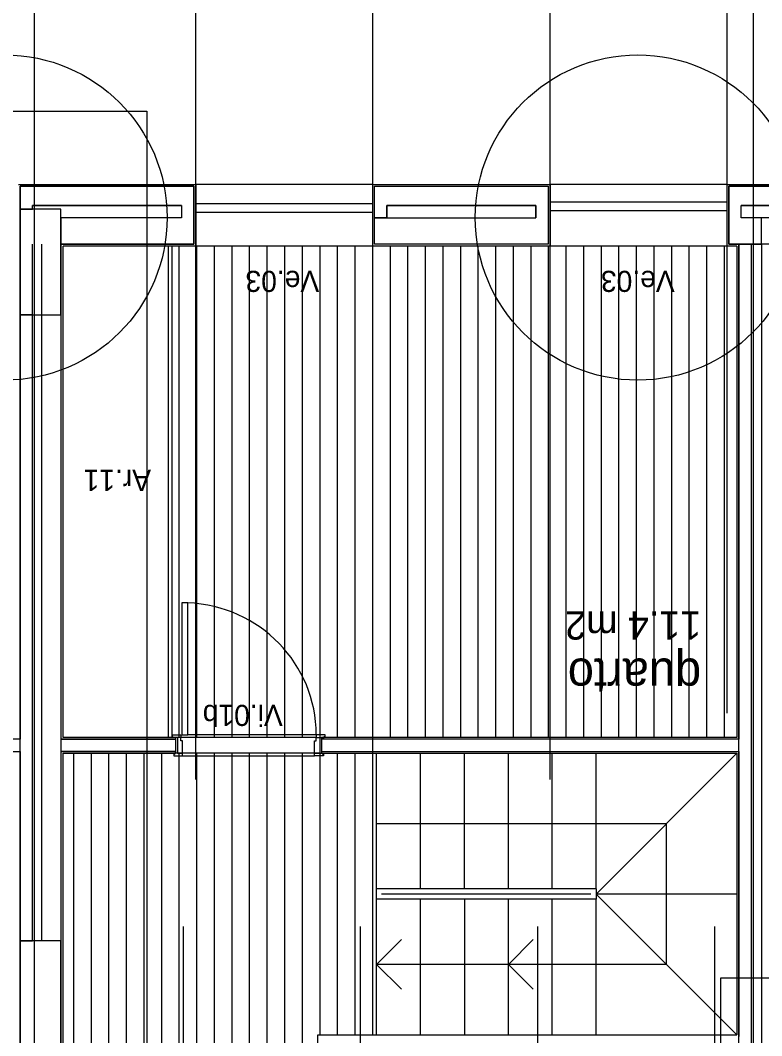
# Model space of a CAD drawing. Extents: x 1278 to 1356, y -253.7 to -224.
# Drawn here: x 1311.39 to 1315.61, y -236.76 to -230.99 of the extents above; entities that cross this region are included whole.
import ezdxf

# ---------------------------------------------------------------- set-up
doc = ezdxf.new("R2010")
doc.units = 0
for name, color, linetype in [('Level 1', 7, 'Continuous'), ('Level 10', 7, 'Continuous'), ('Level 13', 7, 'Continuous'), ('Level 2', 7, 'Continuous'), ('Level 4', 7, 'Continuous'), ('Level 40', 7, 'Continuous'), ('Level 59', 7, 'Continuous'), ('Level 60', 7, 'Continuous'), ('Level 65', 7, 'Continuous'), ('Level 66', 7, 'Continuous'), ('Level 67', 7, 'Continuous'), ('Level 69', 7, 'Continuous'), ('Level 70', 7, 'Continuous'), ('Level 93', 7, 'Continuous')]:
    doc.layers.add(name, color=color, linetype=linetype)

msp = doc.modelspace()

# ---------------------------------------------------------------- linework, layer by layer
at = {"layer": 'Level 1'}
for p, q in [((1311.389, -231.934), (1312.3765, -231.934)), ((1312.3765, -231.934), (1312.3765, -232.264)), ((1313.404, -231.934), (1314.3915, -231.934)), ((1313.404, -232.264), (1313.404, -231.934)), ((1314.3915, -231.934), (1314.3915, -232.264)), ((1315.419, -231.934), (1317.2844, -231.934)), ((1315.419, -232.264), (1315.419, -231.934)), ((1311.459, -232.0639), (1311.459, -232.044)), ((1312.3065, -232.044), (1312.3065, -232.1143)), ((1313.474, -232.1143), (1313.474, -232.044)), ((1314.3215, -232.044), (1314.3215, -232.1143)), ((1315.489, -232.1143), (1315.489, -232.044)), ((1312.3765, -232.264), (1311.6219, -232.264)), ((1314.3915, -232.264), (1313.404, -232.264)), ((1315.6044, -232.264), (1315.419, -232.264)), ((1312.2723, -235.0752), (1311.6219, -235.0752)), ((1312.2723, -235.0652), (1312.2723, -235.1552)), ((1313.1023, -235.0652), (1313.1023, -235.0752)), ((1313.1023, -235.0652), (1313.1023, -235.1552)), ((1311.6219, -235.1452), (1312.2723, -235.1452)), ((1313.1023, -235.1452), (1313.1023, -235.1552)), ((1313.1023, -235.1452), (1315.4744, -235.1452))]:
    msp.add_line(p, q, dxfattribs=at)
for points in [[(1317.2844, -232.264), (1315.6044, -232.264)], [(1315.4744, -235.0752), (1313.1023, -235.0752)]]:
    msp.add_lwpolyline(points, dxfattribs=at)
at = {"layer": 'Level 10'}
for p, q in [((1312.2933, -235.0652), (1312.2933, -232.274)), ((1312.3933, -235.0652), (1312.3933, -232.274)), ((1312.4933, -235.0652), (1312.4933, -232.274)), ((1312.5933, -235.0652), (1312.5933, -232.274)), ((1312.6933, -235.0652), (1312.6933, -232.274)), ((1312.7933, -235.0652), (1312.7933, -232.274)), ((1312.8933, -235.0652), (1312.8933, -232.274)), ((1312.9933, -235.0652), (1312.9933, -232.274)), ((1313.0933, -235.0652), (1313.0933, -232.274)), ((1313.1933, -235.0652), (1313.1933, -232.274)), ((1313.2933, -235.0652), (1313.2933, -232.274)), ((1313.3933, -235.0652), (1313.3933, -232.274)), ((1313.4933, -235.0652), (1313.4933, -232.274)), ((1313.5933, -235.0652), (1313.5933, -232.274)), ((1313.6933, -235.0652), (1313.6933, -232.274)), ((1313.7933, -235.0652), (1313.7933, -232.274)), ((1313.8933, -235.0652), (1313.8933, -232.274)), ((1313.9933, -235.0652), (1313.9933, -232.274)), ((1314.0933, -235.0652), (1314.0933, -232.274)), ((1314.1933, -235.0652), (1314.1933, -232.274)), ((1314.2933, -235.0652), (1314.2933, -232.274)), ((1314.3933, -235.0652), (1314.3933, -232.274)), ((1314.4933, -235.0652), (1314.4933, -232.274)), ((1314.5933, -235.0652), (1314.5933, -232.274)), ((1314.6933, -235.0652), (1314.6933, -232.274)), ((1314.7933, -235.0652), (1314.7933, -232.274)), ((1314.8933, -235.0652), (1314.8933, -232.274)), ((1314.9933, -235.0652), (1314.9933, -232.274)), ((1315.0933, -235.0652), (1315.0933, -232.274)), ((1315.1933, -235.0652), (1315.1933, -232.274)), ((1315.2933, -235.0652), (1315.2933, -232.274)), ((1315.3933, -235.0652), (1315.3933, -232.274)), ((1313.0723, -235.0652), (1312.3023, -235.0652)), ((1311.6933, -243.574), (1311.6933, -235.1552)), ((1311.7933, -243.574), (1311.7933, -235.1552)), ((1311.8933, -243.574), (1311.8933, -235.1552)), ((1311.9933, -243.574), (1311.9933, -235.1552)), ((1312.0933, -243.574), (1312.0933, -235.1552)), ((1312.1933, -243.574), (1312.1933, -235.1552)), ((1312.2933, -243.574), (1312.2933, -235.1552)), ((1313.0623, -235.1552), (1312.3123, -235.1552)), ((1312.3933, -243.574), (1312.3933, -235.1552)), ((1312.4933, -243.574), (1312.4933, -235.1552)), ((1312.5933, -243.574), (1312.5933, -235.1552)), ((1312.6933, -243.574), (1312.6933, -235.1552)), ((1312.7933, -243.574), (1312.7933, -235.1552)), ((1312.8933, -243.574), (1312.8933, -235.1552)), ((1312.9933, -243.574), (1312.9933, -235.1552)), ((1313.0933, -236.7552), (1313.0933, -235.1552)), ((1313.1933, -236.7552), (1313.1933, -235.1552)), ((1313.2933, -236.7552), (1313.2933, -235.1552)), ((1313.3933, -236.7552), (1313.3933, -235.1552))]:
    msp.add_line(p, q, dxfattribs=at)
at = {"layer": 'Level 13'}
for p, q in [((1312.2323, -235.0652), (1312.2323, -232.274)), ((1312.2523, -235.0652), (1312.2523, -232.274)), ((1312.3073, -234.3002), (1312.3073, -235.0502)), ((1312.3423, -234.3002), (1312.3073, -234.3002)), ((1312.3423, -235.0502), (1312.3423, -234.3002)), ((1312.2523, -235.0502), (1312.3023, -235.0502)), ((1312.2523, -235.0602), (1312.2523, -235.0502)), ((1312.2573, -235.0602), (1312.2523, -235.0602)), ((1312.2573, -235.0652), (1312.2573, -235.0602)), ((1312.3023, -235.0652), (1312.2573, -235.0652)), ((1312.2823, -235.0652), (1312.2823, -235.1552)), ((1312.3023, -235.0652), (1312.2823, -235.0652)), ((1312.3023, -235.0502), (1312.3023, -235.0652)), ((1312.3023, -235.0852), (1312.3023, -235.0652)), ((1312.3073, -235.0502), (1312.3423, -235.0502)), ((1313.1223, -235.0502), (1313.0723, -235.0502)), ((1313.0723, -235.0502), (1313.0723, -235.0652)), ((1313.0723, -235.0852), (1313.0723, -235.0652)), ((1313.0723, -235.0652), (1313.0923, -235.0652)), ((1313.0723, -235.0652), (1313.1173, -235.0652)), ((1313.0923, -235.0652), (1313.0923, -235.1552)), ((1313.1173, -235.0652), (1313.1173, -235.0602)), ((1313.1173, -235.0602), (1313.1223, -235.0602)), ((1313.1223, -235.0602), (1313.1223, -235.0502)), ((1312.3123, -235.0852), (1312.3023, -235.0852)), ((1312.3123, -235.1552), (1312.3123, -235.0852)), ((1313.0623, -235.1552), (1313.0623, -235.0852)), ((1313.0623, -235.0852), (1313.0723, -235.0852)), ((1312.2673, -235.1602), (1312.2623, -235.1602)), ((1312.2623, -235.1602), (1312.2623, -235.1702)), ((1312.2623, -235.1702), (1312.3123, -235.1702)), ((1312.3123, -235.1552), (1312.2673, -235.1552)), ((1312.2673, -235.1552), (1312.2673, -235.1602)), ((1312.2823, -235.1552), (1312.3123, -235.1552)), ((1312.3123, -235.1702), (1312.3123, -235.1552)), ((1313.0923, -235.1552), (1313.0623, -235.1552)), ((1313.0623, -235.1702), (1313.0623, -235.1552)), ((1313.0623, -235.1552), (1313.1073, -235.1552)), ((1313.1123, -235.1702), (1313.0623, -235.1702)), ((1313.1073, -235.1552), (1313.1073, -235.1602)), ((1313.1073, -235.1602), (1313.1123, -235.1602)), ((1313.1123, -235.1602), (1313.1123, -235.1702))]:
    msp.add_line(p, q, dxfattribs=at)
at = {"layer": 'Level 2'}
for p, q in [((1313.394, -231.924), (1312.3865, -231.924)), ((1315.409, -231.924), (1314.4015, -231.924)), ((1313.394, -232.034), (1312.3865, -232.034)), ((1315.409, -232.024), (1314.4015, -232.024)), ((1315.409, -232.074), (1314.4015, -232.074)), ((1313.394, -232.084), (1312.3865, -232.084)), ((1313.394, -232.274), (1312.3865, -232.274)), ((1315.409, -232.274), (1314.4015, -232.274)), ((1313.4144, -235.9252), (1313.4144, -235.1552)), ((1313.6644, -235.9252), (1313.6644, -235.1552)), ((1313.9144, -235.9252), (1313.9144, -235.1552)), ((1314.1644, -235.9252), (1314.1644, -235.1552)), ((1314.4144, -235.9252), (1314.4144, -235.1552)), ((1314.6644, -235.9252), (1314.6644, -235.1552)), ((1314.6644, -235.9552), (1315.4644, -235.1552)), ((1313.4144, -235.5552), (1315.0644, -235.5552)), ((1315.0644, -236.3552), (1315.0644, -235.5552)), ((1314.6644, -235.9252), (1313.4144, -235.9252)), ((1313.4144, -235.9852), (1313.4144, -235.9252)), ((1314.6644, -235.9252), (1314.6644, -235.9852)), ((1313.4144, -236.7552), (1313.4144, -235.9852)), ((1314.6644, -235.9852), (1313.4144, -235.9852)), ((1314.6325, -235.9552), (1313.4435, -235.9552)), ((1313.6644, -236.7552), (1313.6644, -235.9852)), ((1313.9144, -235.9852), (1313.9144, -236.7552)), ((1314.1644, -236.7552), (1314.1644, -235.9852)), ((1314.4144, -236.7552), (1314.4144, -235.9852)), ((1315.4644, -235.9552), (1314.6644, -235.9552)), ((1314.6644, -235.9552), (1315.4644, -236.7552)), ((1314.6644, -236.7552), (1314.6644, -235.9852)), ((1313.5558, -236.2137), (1313.4144, -236.3552)), ((1314.3058, -236.2137), (1314.1644, -236.3552)), ((1313.5558, -236.4966), (1313.4144, -236.3552)), ((1314.1644, -236.3552), (1313.4144, -236.3552)), ((1315.0644, -236.3552), (1314.1644, -236.3552)), ((1314.3058, -236.4966), (1314.1644, -236.3552))]:
    msp.add_line(p, q, dxfattribs=at)
at = {"layer": 'Level 4'}
for p, q in [((1313.0723, -235.0502), (1312.3423, -235.0502)), ((1312.3123, -235.1702), (1313.0623, -235.1702))]:
    msp.add_line(p, q, dxfattribs=at)
msp.add_ellipse((1312.3091, -235.0502), major_axis=(-0.7632, 0), ratio=0.982661, start_param=3.141593, end_param=4.668897, dxfattribs=at)
at = {"layer": 'Level 59'}
msp.add_lwpolyline([(1312.108, -245.3846), (1306.9649, -245.3846), (1306.9649, -231.5072), (1312.108, -231.5072)], close=True, dxfattribs=at)
at = {"layer": 'Level 65'}
for p, q in [((1311.379, -231.924), (1312.3865, -231.924)), ((1312.3865, -231.924), (1312.3865, -232.274)), ((1313.394, -232.274), (1313.394, -231.924)), ((1313.394, -231.924), (1314.4015, -231.924)), ((1314.4015, -231.924), (1314.4015, -232.274)), ((1315.409, -231.924), (1317.2944, -231.924)), ((1315.409, -232.274), (1315.409, -231.924)), ((1312.3865, -232.274), (1311.6319, -232.274)), ((1311.6319, -235.0652), (1311.6319, -232.274)), ((1311.6319, -235.0652), (1311.6319, -232.274)), ((1311.6319, -235.0652), (1311.6319, -232.274)), ((1314.4015, -232.274), (1313.394, -232.274)), ((1315.4644, -232.274), (1315.4644, -235.0652)), ((1312.2723, -235.0652), (1311.6319, -235.0652)), ((1311.6319, -235.1552), (1312.2723, -235.1552)), ((1311.6319, -243.574), (1311.6319, -235.1552)), ((1311.6319, -240.7363), (1311.6319, -235.1552)), ((1313.1023, -235.1552), (1315.4644, -235.1552)), ((1315.4644, -235.1552), (1315.4644, -236.7552)), ((1313.0819, -236.7552), (1315.4644, -236.7552)), ((1313.0819, -237.1748), (1313.0819, -236.7552))]:
    msp.add_line(p, q, dxfattribs=at)
for points in [[(1315.4644, -232.274), (1315.409, -232.274)], [(1315.4644, -235.0652), (1313.1023, -235.0652)]]:
    msp.add_lwpolyline(points, dxfattribs=at)
at = {"layer": 'Level 66'}
for p, q in [((1311.389, -237.0363), (1311.389, -231.934)), ((1312.3065, -232.044), (1311.459, -232.044)), ((1313.474, -232.044), (1314.3215, -232.044)), ((1317.2144, -232.044), (1315.489, -232.044)), ((1312.3065, -232.1143), (1311.619, -232.1143)), ((1313.474, -232.1143), (1314.3215, -232.1143)), ((1317.2144, -232.1143), (1315.489, -232.1143)), ((1311.459, -236.2213), (1311.459, -232.264)), ((1311.5119, -236.2213), (1311.5119, -232.264)), ((1311.6219, -243.584), (1311.6219, -232.264)), ((1311.6219, -243.584), (1311.6219, -232.264)), ((1311.6219, -243.584), (1311.6219, -232.264)), ((1311.6219, -243.584), (1311.6219, -232.264)), ((1311.6219, -243.584), (1311.6219, -232.264)), ((1315.4744, -232.264), (1315.4744, -235.0752)), ((1315.5444, -232.264), (1315.5444, -238.7963)), ((1315.6044, -232.264), (1315.6044, -242.1013)), ((1315.4744, -235.1452), (1315.4744, -236.7652))]:
    msp.add_line(p, q, dxfattribs=at)
for points in [[(1311.389, -232.6639), (1311.619, -232.6639), (1311.619, -232.0639), (1311.389, -232.0639)], [(1311.389, -232.6639), (1311.619, -232.6639), (1311.619, -232.0639), (1311.389, -232.0639)], [(1311.389, -236.9213), (1311.619, -236.9213), (1311.619, -236.2213), (1311.389, -236.2213)]]:
    msp.add_lwpolyline(points, close=True, dxfattribs=at)
at = {"layer": 'Level 67'}
for points in [[(1311.459, -232.044), (1312.3065, -232.044), (1312.3065, -232.1143), (1311.619, -232.1143), (1311.619, -232.264), (1312.3765, -232.264), (1312.3765, -231.934), (1311.389, -231.934), (1311.389, -232.0639), (1311.459, -232.0639)], [(1314.3915, -231.934), (1314.3915, -232.264), (1313.404, -232.264), (1313.404, -232.1143), (1314.3215, -232.1143), (1314.3215, -232.044), (1313.474, -232.044), (1313.474, -232.1143), (1313.404, -232.1143), (1313.404, -231.934)], [(1315.6044, -232.264), (1315.6044, -232.1143), (1315.489, -232.1143), (1315.489, -232.044), (1317.2144, -232.044), (1317.2144, -232.1143), (1315.7544, -232.1143), (1315.7544, -232.264), (1317.2844, -232.264), (1317.2844, -231.934), (1315.419, -231.934), (1315.419, -232.264)], [(1315.5444, -232.264), (1315.5444, -238.7963), (1315.4744, -238.7963), (1315.4744, -232.264)], [(1311.459, -232.6639), (1311.389, -232.6639), (1311.389, -235.0752), (1309.0723, -235.0752), (1309.0723, -235.1452), (1311.389, -235.1452), (1311.389, -236.2213), (1311.459, -236.2213)], [(1311.619, -236.2213), (1311.5119, -236.2213), (1311.5119, -232.6639), (1311.619, -232.6639)], [(1312.2723, -235.0752), (1312.2723, -235.1452), (1311.6219, -235.1452), (1311.6219, -235.0752)], [(1315.4744, -235.0752), (1313.1023, -235.0752), (1313.1023, -235.1452), (1315.4744, -235.1452)]]:
    msp.add_lwpolyline(points, close=True, dxfattribs=at)
at = {"layer": 'Level 69'}
msp.add_lwpolyline([(1318.7233, -238.934), (1315.3724, -238.934), (1315.3724, -236.4315), (1318.7233, -236.4315)], close=True, dxfattribs=at)
for centre in [(1311.3004, -232.1122), (1314.9002, -232.1122)]:
    msp.add_circle(centre, 0.9238, dxfattribs=at)
at = {"layer": 'Level 70'}
for p, q in [((1311.469, -250.7923), (1311.469, -229.6198)), ((1315.5589, -250.7923), (1315.5589, -229.6198))]:
    msp.add_line(p, q, dxfattribs=at)
at = {"layer": 'Level 93'}
for p, q in [((1312.3865, -235.3039), (1312.3865, -224.3117)), ((1313.394, -235.3039), (1313.394, -224.3117)), ((1314.4015, -235.3039), (1314.4015, -224.3117)), ((1315.409, -234.928), (1315.409, -224.3117)), ((1312.3165, -246.757), (1312.3165, -236.1407)), ((1313.324, -246.757), (1313.324, -236.1407)), ((1314.3315, -246.757), (1314.3315, -236.1407)), ((1315.339, -246.757), (1315.339, -236.1407))]:
    msp.add_line(p, q, dxfattribs=at)

# ---------------------------------------------------------------- texts
at = {"layer": 'Level 40'}
for s, rotation, p in [('Ve.03', 180.00001, (1313.0889, -232.4145)), ('Ve.03', 180.00001, (1315.1102, -232.4145)), ('Ar.11', 179.99999, (1312.1325, -233.5449)), ('Vi.01b', 180.00001, (1312.8815, -234.8804))]:
    msp.add_text(s, height=0.12, rotation=rotation, dxfattribs=at).set_placement(p)
at = {"layer": 'Level 60'}
for s, height, p in [('11.4 m2', 0.16, (1315.2606, -234.3497)), ('quarto', 0.2, (1315.2606, -234.6175))]:
    msp.add_text(s, height=height, rotation=180, dxfattribs=at).set_placement(p)

doc.saveas('drawing.dxf')
